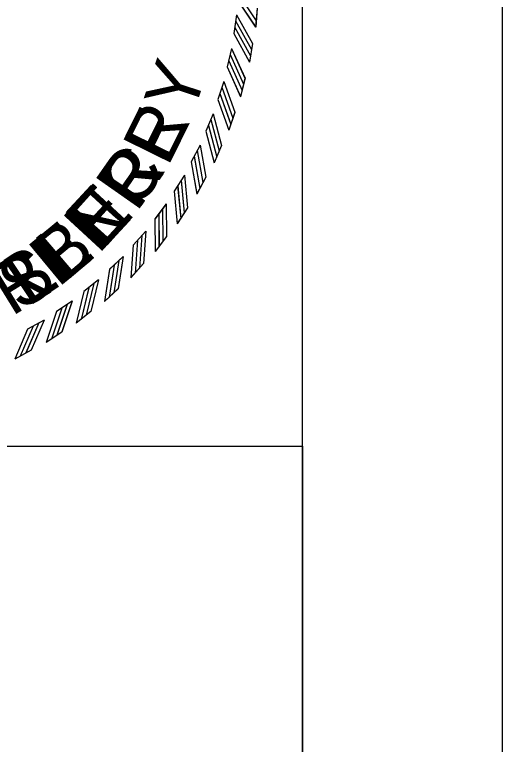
# Model space of a CAD drawing. Extents: x 0 to 1228740, y 0 to 152440.
# Drawn here: x 32.593 to 34, y 16.545 to 18.649 of the extents above; entities that cross this region are included whole.
import ezdxf

# ---------------------------------------------------------------- set-up
doc = ezdxf.new("R2010")
doc.units = 0
for name, color, linetype in [('R_Border', 7, 'Continuous'), ('R_No Plot', 7, 'Continuous'), ('STAMP_BOL', 7, 'Continuous'), ('STAMP_LKM', 7, 'Continuous'), ('STAMP_SPT', 7, 'Continuous')]:
    doc.layers.add(name, color=color, linetype=linetype)

msp = doc.modelspace()

# ---------------------------------------------------------------- linework, layer by layer
at = {"layer": 'R_Border'}
msp.add_line((33.4231, 0.5768), (33.4231, 21.4232), dxfattribs=at)
msp.add_lwpolyline([(33.9999, 22), (0, 22), (0, 0), (33.9999, 0)], close=True, dxfattribs=at)
at = {"layer": 'R_No Plot'}
for points in [[(33.4231, 17.4052), (33.4231, 0.5768), (1.516, 0.5768), (1.516, 21.4232), (25.1971, 21.4232), (25.1971, 20.4352), (28.7491, 20.4352), (28.7491, 20.0782), (29.1131, 20.0782), (29.1131, 20.1432), (30.6665, 20.1432)], [(33.4231, 17.4052), (33.4231, 10.8708), (1.516, 10.8708), (1.516, 21.4232), (25.1971, 21.4232), (25.1971, 20.4352), (28.7491, 20.4352), (28.7491, 20.0782), (29.1131, 20.0782), (29.1131, 20.1432), (30.6665, 20.1432)], [(30.6665, 20.1432), (30.6665, 17.4052), (33.4231, 17.4052)], [(30.6665, 20.1432), (30.6665, 17.4052), (33.4231, 17.4052)]]:
    msp.add_lwpolyline(points, dxfattribs=at)
at = {"layer": 'STAMP_BOL'}
for p, q in [((33.2926, 18.6676), (33.2886, 18.6134)), ((33.2337, 18.6483), (33.2252, 18.5944)), ((33.2793, 18.5659), (33.2709, 18.5122)), ((33.2191, 18.5515), (33.2062, 18.4985)), ((33.1965, 18.4562), (33.1793, 18.4045)), ((33.2578, 18.4656), (33.2449, 18.4128)), ((33.1662, 18.3632), (33.1448, 18.313)), ((33.228, 18.3675), (33.2108, 18.3158)), ((33.1283, 18.2729), (33.1028, 18.2247)), ((33.1902, 18.2721), (33.1689, 18.2221)), ((33.0831, 18.1861), (33.0536, 18.1402)), ((33.1447, 18.1802), (33.1193, 18.1321)), ((33.0308, 18.1033), (32.9977, 18.06)), ((33.0918, 18.0924), (33.0624, 18.0465)), ((32.9719, 18.0252), (32.9353, 17.9847)), ((33.0318, 18.0092), (32.9987, 17.9659)), ((32.9067, 17.9521), (32.8669, 17.9148)), ((32.9651, 17.9313), (32.9286, 17.8909)), ((32.8358, 17.8847), (32.793, 17.8508)), ((32.8922, 17.8591), (32.8525, 17.8219)), ((32.7595, 17.8234), (32.7141, 17.7932)), ((32.8136, 17.7932), (32.7709, 17.7594)), ((32.6784, 17.7686), (32.6306, 17.7422)), ((32.7298, 17.734), (32.6845, 17.7039)), ((32.6414, 17.682), (32.5938, 17.6557))]:
    msp.add_line(p, q, dxfattribs=at)
for points in [[(33.2378, 18.7097), (33.2901, 18.6314)], [(33.2363, 18.6916), (33.2886, 18.6133)], [(33.2337, 18.6483), (33.2793, 18.566)], [(33.2308, 18.6311), (33.2764, 18.5487)], [(33.2283, 18.6123), (33.2739, 18.53)], [(33.2253, 18.5944), (33.2709, 18.5121)], [(33.2191, 18.5515), (33.2578, 18.4657)], [(33.2107, 18.5161), (33.2494, 18.4303)], [(33.2148, 18.5346), (33.2535, 18.4487)], [(33.2062, 18.4985), (33.2449, 18.4127)], [(33.1965, 18.4563), (33.228, 18.3676)], [(33.1908, 18.4397), (33.2223, 18.351)], [(33.1853, 18.4217), (33.2167, 18.3329)], [(33.1794, 18.4045), (33.2108, 18.3158)], [(33.1592, 18.3472), (33.1832, 18.2562)], [(33.1662, 18.3632), (33.1902, 18.2722)], [(33.1521, 18.3297), (33.1761, 18.2386)], [(33.1448, 18.3131), (33.1689, 18.222)], [(33.1283, 18.273), (33.1447, 18.1803)], [(33.1199, 18.2576), (33.1364, 18.1649)], [(33.1028, 18.2247), (33.1193, 18.132)], [(33.1115, 18.2407), (33.1279, 18.148)], [(33.083, 18.1862), (33.0918, 18.0924)], [(33.0735, 18.1715), (33.0822, 18.0778)], [(33.0537, 18.1402), (33.0624, 18.0465)], [(33.0636, 18.1554), (33.0724, 18.0616)], [(33.0308, 18.1034), (33.0318, 18.0093)], [(33.0089, 18.0743), (33.0099, 17.9802)], [(33.02, 18.0896), (33.021, 17.9955)], [(32.9978, 18.06), (32.9987, 17.9659)], [(32.96, 18.0124), (32.9532, 17.9185)], [(32.9719, 18.0253), (32.9651, 17.9313)], [(32.9477, 17.9981), (32.9409, 17.9042)], [(32.9354, 17.9847), (32.9286, 17.8908)], [(32.9067, 17.9522), (32.8922, 17.8592)], [(32.8804, 17.9271), (32.8658, 17.8341)], [(32.8939, 17.9403), (32.8793, 17.8473)], [(32.867, 17.9148), (32.8525, 17.8218)], [(32.8358, 17.8848), (32.8136, 17.7933)], [(32.822, 17.874), (32.7998, 17.7825)], [(32.7931, 17.8508), (32.7709, 17.7593)], [(32.8074, 17.862), (32.7852, 17.7705)], [(32.7595, 17.8235), (32.7298, 17.7341)], [(32.7293, 17.8031), (32.6997, 17.7137)], [(32.7448, 17.8139), (32.7152, 17.7245)], [(32.7142, 17.7932), (32.6845, 17.7038)], [(32.663, 17.7603), (32.6261, 17.6737)], [(32.6784, 17.7687), (32.6415, 17.6821)], [(32.6307, 17.7422), (32.5938, 17.6556)], [(32.6467, 17.7508), (32.6097, 17.6642)]]:
    msp.add_lwpolyline(points, dxfattribs=at)
at = {"layer": 'STAMP_LKM'}
for p, q in [((33.2926, 18.6677), (33.2886, 18.6134)), ((33.2337, 18.6483), (33.2253, 18.5945)), ((33.2794, 18.566), (33.2709, 18.5123)), ((33.2191, 18.5516), (33.2062, 18.4986)), ((33.1966, 18.4563), (33.1794, 18.4046)), ((33.2578, 18.4657), (33.2449, 18.4129)), ((33.1663, 18.3633), (33.1448, 18.3131)), ((33.2281, 18.3676), (33.2109, 18.316)), ((33.1283, 18.273), (33.1028, 18.2248)), ((33.1903, 18.2722), (33.1689, 18.2222)), ((33.0831, 18.1862), (33.0537, 18.1403)), ((33.1448, 18.1803), (33.1193, 18.1322)), ((33.0309, 18.1035), (32.9978, 18.0601)), ((33.0918, 18.0925), (33.0625, 18.0467)), ((32.9719, 18.0253), (32.9354, 17.9848)), ((33.0318, 18.0093), (32.9988, 17.9661)), ((32.9068, 17.9523), (32.867, 17.915)), ((32.9651, 17.9314), (32.9286, 17.891)), ((32.8358, 17.8849), (32.7931, 17.851)), ((32.8922, 17.8593), (32.8525, 17.822)), ((32.7595, 17.8236), (32.7142, 17.7933)), ((32.8136, 17.7934), (32.771, 17.7596)), ((32.6784, 17.7688), (32.6307, 17.7424)), ((32.7299, 17.7342), (32.6846, 17.704)), ((32.6415, 17.6822), (32.5939, 17.6558))]:
    msp.add_line(p, q, dxfattribs=at)
for points in [[(33.2378, 18.7097), (33.2901, 18.6315)], [(33.2363, 18.6917), (33.2886, 18.6134)], [(33.2337, 18.6484), (33.2793, 18.5661)], [(33.2308, 18.6311), (33.2765, 18.5488)], [(33.2283, 18.6124), (33.2739, 18.5301)], [(33.2253, 18.5945), (33.2709, 18.5122)], [(33.2191, 18.5516), (33.2578, 18.4658)], [(33.2107, 18.5162), (33.2494, 18.4304)], [(33.2148, 18.5347), (33.2535, 18.4488)], [(33.2063, 18.4986), (33.245, 18.4128)], [(33.1966, 18.4564), (33.228, 18.3677)], [(33.1909, 18.4398), (33.2223, 18.3511)], [(33.1853, 18.4218), (33.2168, 18.333)], [(33.1794, 18.4046), (33.2109, 18.3159)], [(33.1592, 18.3473), (33.1832, 18.2563)], [(33.1662, 18.3633), (33.1903, 18.2723)], [(33.1521, 18.3298), (33.1762, 18.2387)], [(33.1449, 18.3132), (33.1689, 18.2221)], [(33.1283, 18.2731), (33.1448, 18.1804)], [(33.12, 18.2577), (33.1364, 18.165)], [(33.1029, 18.2249), (33.1193, 18.1322)], [(33.1115, 18.2408), (33.128, 18.1481)], [(33.0831, 18.1863), (33.0918, 18.0926)], [(33.0735, 18.1717), (33.0822, 18.0779)], [(33.0538, 18.1403), (33.0625, 18.0466)], [(33.0637, 18.1555), (33.0724, 18.0618)], [(33.0309, 18.1036), (33.0318, 18.0094)], [(33.009, 18.0745), (33.0099, 17.9803)], [(33.0201, 18.0897), (33.0211, 17.9956)], [(32.9978, 18.0602), (32.9988, 17.966)], [(32.9601, 18.0125), (32.9533, 17.9186)], [(32.972, 18.0254), (32.9651, 17.9315)], [(32.9477, 17.9982), (32.9409, 17.9043)], [(32.9355, 17.9849), (32.9286, 17.891)], [(32.9068, 17.9524), (32.8923, 17.8593)], [(32.8804, 17.9273), (32.8659, 17.8343)], [(32.8939, 17.9405), (32.8794, 17.8475)], [(32.8671, 17.915), (32.8525, 17.822)], [(32.8358, 17.885), (32.8137, 17.7935)], [(32.822, 17.8742), (32.7998, 17.7827)], [(32.7932, 17.851), (32.771, 17.7595)], [(32.8075, 17.8621), (32.7853, 17.7706)], [(32.7596, 17.8236), (32.7299, 17.7343)], [(32.7294, 17.8032), (32.6997, 17.7139)], [(32.7449, 17.8141), (32.7152, 17.7247)], [(32.7142, 17.7933), (32.6846, 17.704)], [(32.6631, 17.7605), (32.6261, 17.6739)], [(32.6785, 17.7688), (32.6415, 17.6822)], [(32.6308, 17.7424), (32.5939, 17.6558)], [(32.6467, 17.751), (32.6098, 17.6644)]]:
    msp.add_lwpolyline(points, dxfattribs=at)
at = {"layer": 'STAMP_SPT'}
for p, q in [((33.2925, 18.6677), (33.2885, 18.6135)), ((33.2337, 18.6484), (33.2252, 18.5945)), ((33.2793, 18.566), (33.2708, 18.5123)), ((33.2191, 18.5516), (33.2062, 18.4986)), ((33.1965, 18.4563), (33.1793, 18.4046)), ((33.2577, 18.4657), (33.2449, 18.4129)), ((33.1662, 18.3633), (33.1447, 18.3131)), ((33.228, 18.3676), (33.2108, 18.316)), ((33.1283, 18.273), (33.1027, 18.2248)), ((33.1902, 18.2722), (33.1688, 18.2222)), ((33.083, 18.1863), (33.0536, 18.1403)), ((33.1447, 18.1803), (33.1192, 18.1323)), ((33.0308, 18.1035), (32.9977, 18.0601)), ((33.0917, 18.0925), (33.0624, 18.0467)), ((32.9719, 18.0253), (32.9353, 17.9849)), ((33.0317, 18.0093), (32.9987, 17.9661)), ((32.9067, 17.9523), (32.8669, 17.915)), ((32.965, 17.9314), (32.9286, 17.8911)), ((32.8357, 17.8849), (32.793, 17.851)), ((32.8922, 17.8593), (32.8525, 17.8221)), ((32.7595, 17.8236), (32.7141, 17.7933)), ((32.8136, 17.7934), (32.7709, 17.7596)), ((32.6784, 17.7688), (32.6306, 17.7424)), ((32.7298, 17.7342), (32.6845, 17.704)), ((32.6414, 17.6822), (32.5938, 17.6558))]:
    msp.add_line(p, q, dxfattribs=at)
for points in [[(33.2378, 18.7098), (33.29, 18.6315)], [(33.2363, 18.6917), (33.2885, 18.6134)], [(33.2336, 18.6484), (33.2793, 18.5661)], [(33.2307, 18.6312), (33.2764, 18.5488)], [(33.2282, 18.6124), (33.2739, 18.5301)], [(33.2252, 18.5945), (33.2709, 18.5122)], [(33.219, 18.5517), (33.2577, 18.4658)], [(33.2107, 18.5162), (33.2493, 18.4304)], [(33.2147, 18.5347), (33.2534, 18.4489)], [(33.2062, 18.4986), (33.2449, 18.4128)], [(33.1965, 18.4564), (33.228, 18.3677)], [(33.1908, 18.4398), (33.2223, 18.3511)], [(33.1852, 18.4218), (33.2167, 18.3331)], [(33.1793, 18.4046), (33.2108, 18.3159)], [(33.1591, 18.3473), (33.1832, 18.2563)], [(33.1662, 18.3634), (33.1902, 18.2723)], [(33.1521, 18.3298), (33.1761, 18.2388)], [(33.1448, 18.3132), (33.1688, 18.2222)], [(33.1282, 18.2731), (33.1447, 18.1804)], [(33.1199, 18.2577), (33.1364, 18.165)], [(33.1028, 18.2249), (33.1193, 18.1322)], [(33.1114, 18.2408), (33.1279, 18.1481)], [(33.083, 18.1863), (33.0917, 18.0926)], [(33.0734, 18.1717), (33.0822, 18.0779)], [(33.0537, 18.1404), (33.0624, 18.0466)], [(33.0636, 18.1555), (33.0723, 18.0618)], [(33.0308, 18.1036), (33.0317, 18.0094)], [(33.0089, 18.0745), (33.0098, 17.9803)], [(33.02, 18.0898), (33.021, 17.9956)], [(32.9977, 18.0602), (32.9987, 17.966)], [(32.96, 18.0125), (32.9532, 17.9186)], [(32.9719, 18.0254), (32.9651, 17.9315)], [(32.9477, 17.9982), (32.9408, 17.9043)], [(32.9354, 17.9849), (32.9286, 17.891)], [(32.9067, 17.9524), (32.8922, 17.8594)], [(32.8803, 17.9273), (32.8658, 17.8343)], [(32.8938, 17.9405), (32.8793, 17.8475)], [(32.867, 17.915), (32.8525, 17.822)], [(32.8358, 17.885), (32.8136, 17.7935)], [(32.8219, 17.8742), (32.7998, 17.7827)], [(32.7931, 17.851), (32.7709, 17.7595)], [(32.8074, 17.8621), (32.7852, 17.7706)], [(32.7595, 17.8237), (32.7298, 17.7343)], [(32.7293, 17.8032), (32.6997, 17.7139)], [(32.7448, 17.8141), (32.7152, 17.7247)], [(32.7142, 17.7933), (32.6845, 17.704)], [(32.663, 17.7605), (32.6261, 17.6739)], [(32.6784, 17.7688), (32.6415, 17.6823)], [(32.6307, 17.7424), (32.5938, 17.6558)], [(32.6467, 17.751), (32.6097, 17.6644)]]:
    msp.add_lwpolyline(points, dxfattribs=at)

# ---------------------------------------------------------------- texts
at = {"layer": 'STAMP_BOL'}
for s, rotation, p in [('E', 63.7362, (33.0351, 18.2081)), ('C', 56.0754, (32.9507, 18.0834)), ('N', 47.3202, (32.8349, 17.9561)), ('E', 39.6594, (32.7186, 17.8603)), ('R', 31.6338, (32.5843, 17.7776))]:
    msp.add_text(s, height=0.1503, rotation=rotation, dxfattribs=at).set_placement(p)
at = {"layer": 'STAMP_LKM'}
for s, rotation, p in [('R', 54.9491, (32.9445, 18.0769)), ('E', 47.1522, (32.8415, 17.9636)), ('L', 40.4692, (32.7416, 17.8784)), ('L', 33.7862, (32.6325, 17.8054))]:
    msp.add_text(s, height=0.153, rotation=rotation, dxfattribs=at).set_placement(p)
at = {"layer": 'STAMP_SPT'}
for s, rotation, p in [('Y', 71.7733, (33.1072, 18.3567)), ('R', 63.7477, (33.0384, 18.2148)), ('R', 55.7221, (32.9504, 18.084)), ('E', 48.0613, (32.8502, 17.9717)), ('B', 40.0357, (32.7301, 17.8695)), ('S', 32.7397, (32.6095, 17.7919))]:
    msp.add_text(s, height=0.1503, rotation=rotation, dxfattribs=at).set_placement(p)

doc.saveas('drawing.dxf')
